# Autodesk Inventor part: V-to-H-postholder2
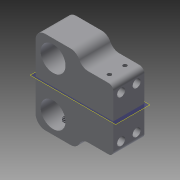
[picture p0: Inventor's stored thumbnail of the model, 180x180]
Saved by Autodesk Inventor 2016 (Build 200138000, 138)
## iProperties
Created: 2014-08
Part Number: V-to-H-postholder2
Material: Generic
Document SubType Name: Modeling
Designer: James
Density: 1 g/cm^3
Appearance: Default
Author: James
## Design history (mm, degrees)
sketch "Sketch1"
  geometry: L1 (-41.481, 18.304)-(-25.481, 18.304); L2 (-25.481, 18.304)-(-25.481, -24.696); L3 (-25.481, -24.696)-(-41.481, -24.696); L4 (-41.481, -24.696)-(-41.481, 18.304); 1 further point
  constraints: 8 end point, 2 parallel, 1 horizontal, 1 perpendicular
  dimensions: "d0" = 43 distance between parallel lines of L3 L1; "d1" = 16 distance between parallel lines of L4 L2
extrude "Extrusion1" new body sketch "Sketch1" distance "d2" = 40; taper "d3" = 0 deg
sketch "Sketch2"
  geometry: L1 (0, 0)-(0, 43) reference; L2 (0, 0)-(40, 0) reference; L3 (0, 43)-(40, 43) reference; 3 further points
  dimensions: "d5" = 9 distance from line of L3 point (9, 34) (= d7); "d6" = 9 distance from line of L2 point (9, 9) (= d7); "d7" = 9 distance from line of point (9, 34) L1; "d8" = 9 distance from line of point (9, 9) L1 (= d7)
hole "Hole1" sketch "Sketch2" at (9, 34), (9, 9) diameter "d9" = 12.8; stored, may be unused: countersink angle "d13" = 82 deg, drill point angle "d15" = 118 deg; dims "d10" = 6, "d11" = 3.023, "d12" = 2, "d14" = 8
sketch "Sketch4"
  geometry: L1 (0, 16)-(0, 0) reference; L2 (0, 0)-(-40, 0) reference; 2 further points
  dimensions: "d28" = 9 distance from line of L1 point (-9, 8); "d76" = 8 distance from line of L2 point (-9, 8)
hole "Hole3" sketch "Sketch4" at (-9, 8) diameter "d29" = 4.917; stored, may be unused: countersink angle "d33" = 82 deg, drill point angle "d35" = 118 deg; dims "d30" = 6, "d31" = 3.023, "d32" = 2, "d34" = 10
sketch "Sketch7"
  geometry: L1 (24.696, -41.481)-(24.696, -25.481) reference; L2 (24.696, -25.481)-(-18.304, -25.481) reference; 3 further points
  dimensions: "d55" = 4 distance from line of L2 point (14.096, -29.481); "d56" = 10.6 distance from line of L1 point (14.096, -29.481) (computed from d85); "d57" = 10.6 distance from line of L1 point (14.096, -37.481) (= d56); "d58" = 8 distance of point (14.096, -29.481) point (14.096, -37.481); "d85" = 43 distance of L1.end L2.end (derived)
hole "Hole6" sketch "Sketch7" at (14.096, -29.481), (14.096, -37.481) diameter "d59" = 4.1; stored, may be unused: countersink angle "d63" = 82 deg, drill point angle "d65" = 118 deg; dims "d60" = 6, "d61" = 3.023, "d62" = 2, "d64" = 20
sketch "Sketch8"
  geometry: L1 (0, 16)-(-40, 16) reference; L2 (-40, 0)-(-40, 16) reference; 3 further points
  dimensions: "d66" = 4 distance from line of L1 point (-34, 12); "d67" = 6 distance from line of L2 point (-34, 12); "d68" = 8 distance of point (-34, 12) point (-34, 4)
hole "Hole7" sketch "Sketch8" at (-34, 12), (-34, 4) diameter "d69" = 2.013; stored, may be unused: countersink angle "d73" = 82 deg, drill point angle "d75" = 118 deg; dims "d70" = 6, "d71" = 3.023, "d72" = 2, "d74" = 13
pattern_linear "Rectangular Pattern1" dims "d84" = 21.8
workplane "Work Plane1"
mirror "Mirror1"
sketch "Sketch10"
  geometry: L1 (24.696, -41.481)-(24.696, -25.481) reference; L2 (24.696, -25.481)-(-18.304, -25.481) reference; L3 (24.696, -41.481)-(19.096, -41.481); L4 (19.096, -41.481)-(19.096, -25.481); L5 (19.096, -25.481)-(24.696, -25.481); L6 (24.696, -25.481)-(24.696, -41.481); C1 r 2.05 at (14.096, -37.481) reference; C2 r 2.05 at (14.096, -29.481) reference; 3 further points
  constraints: 8 end point, 2 coincident, 2 parallel, 1 horizontal, 1 perpendicular, 1 point on line
  dimensions: "d86" = 5 distance from line of point (14.096, -29.481) L4
extrude "Extrusion3" cut sketch "Sketch10" distance "d87" = 18; taper "d88" = 0 deg
mirror "Mirror2"
fillet "Fillet2" dims "d89" = 5
fillet "Fillet3" dims "d90" = 2.5
body "Solid1"
